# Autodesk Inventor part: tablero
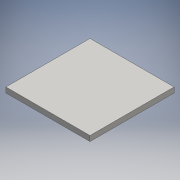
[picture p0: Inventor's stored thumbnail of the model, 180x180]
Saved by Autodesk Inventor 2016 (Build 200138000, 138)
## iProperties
Created: 2016-06
Part Number: tablero
Material: Generic
Document SubType Name: Modeling
Designer: yesi alvarez
Mass: 32000 g
Surface Area: 14400 cm^2
Volume: 32000 cm^3
Density: 1 g/cm^3
Appearance: Default
Author: yesi alvarez
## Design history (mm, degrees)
sketch "Sketch1"
  geometry: L1 (0, 0)-(800, 0); L2 (800, 0)-(800, 800); L3 (800, 800)-(0, 800); L4 (0, 800)-(0, 0)
  constraints: 8 end point, 2 parallel, 1 horizontal, 1 perpendicular
  dimensions: "d0" = 800 distance of L3.end L2.end; "d1" = 800 distance of L2.end L1.end
extrude "Extrusion1" new body sketch "Sketch1" distance "d2" = 50; taper "d3" = 0 deg
body "Solid1"
